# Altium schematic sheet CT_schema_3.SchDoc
size 321 x 189 mm
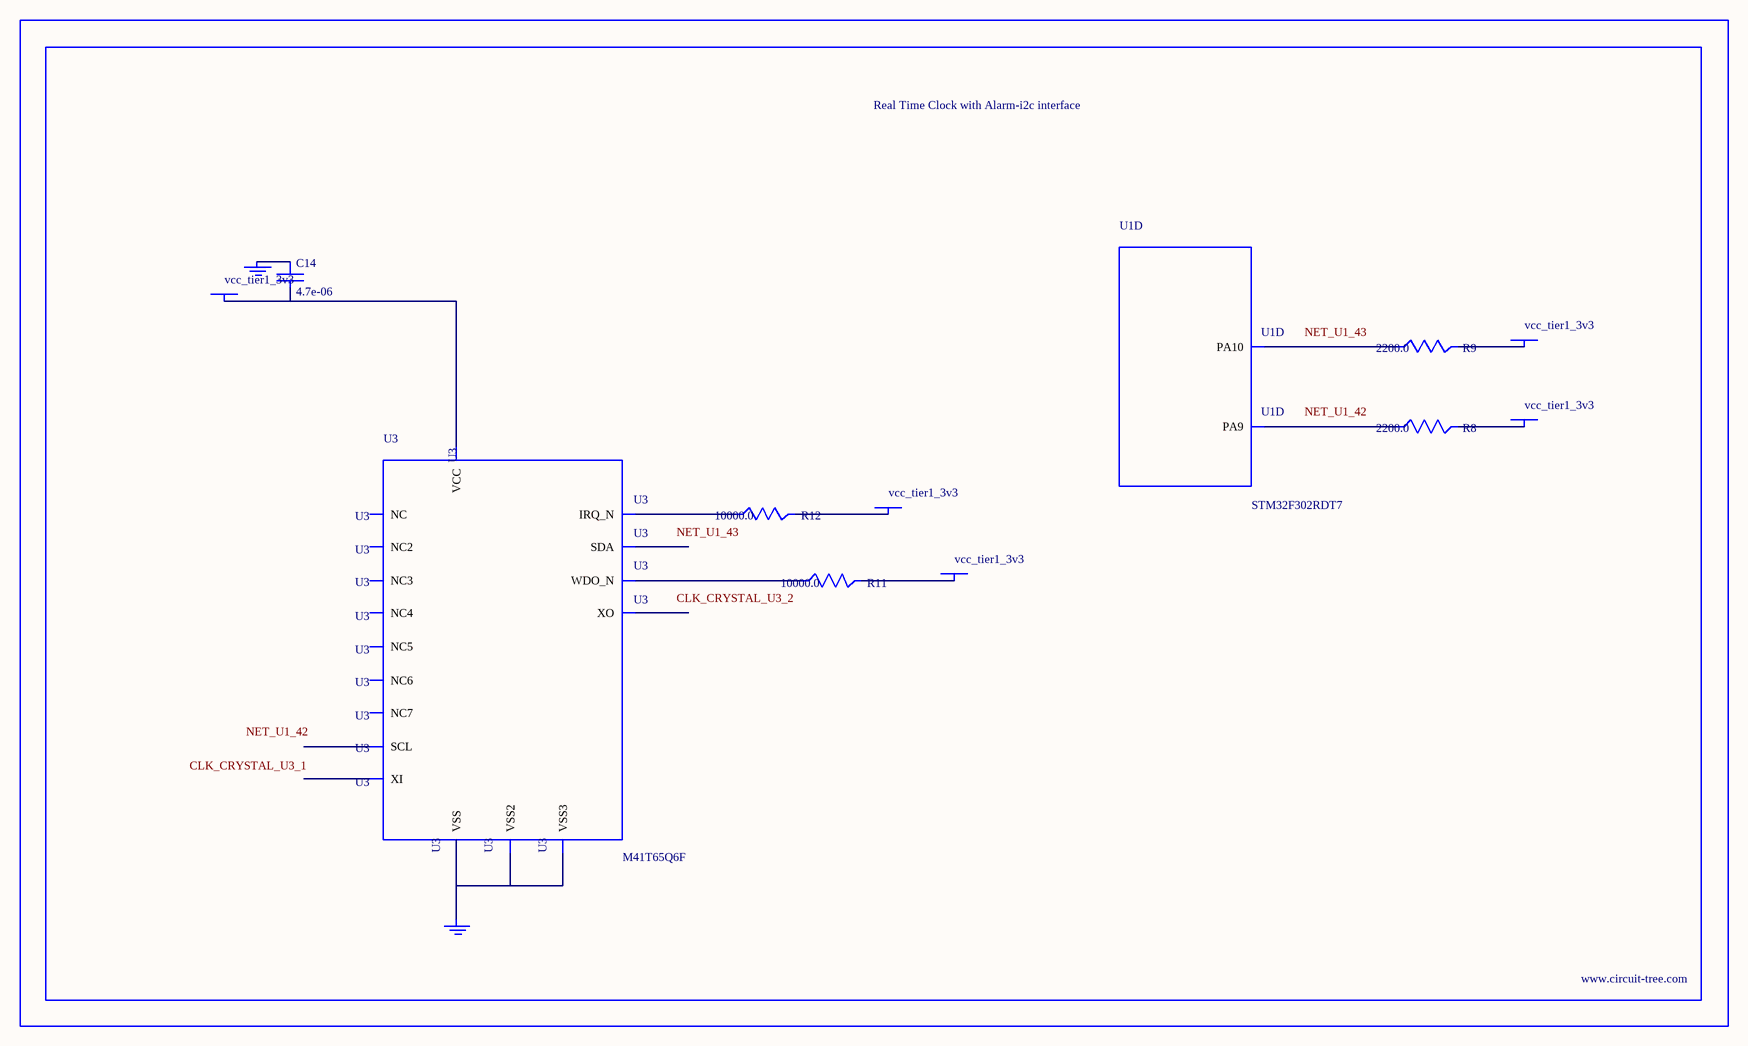
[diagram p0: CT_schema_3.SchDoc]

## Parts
BORDER2  (no value)
C14  4.7e-06  [C0805]
GND_INSTANCE_2_0  (no value)
GND_INSTANCE_2_1  (no value)
POWER_INSTANCE_2_0  vcc_tier1_3v3
POWER_INSTANCE_2_1  vcc_tier1_3v3
POWER_INSTANCE_2_2  vcc_tier1_3v3
POWER_INSTANCE_2_3  vcc_tier1_3v3
POWER_INSTANCE_2_4  vcc_tier1_3v3
R8  2200.0  [R0603]
R9  2200.0  [R0603]
R11  10000.0  [R0603]
R12  10000.0  [R0603]
U1  STM32F302RDT7  [LQFP64]  (part D of 7)
U3  M41T65Q6F  [M41T65_QFN-16]

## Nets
NetC14_1: C14.1 GND_INSTANCE_2_0.0(GND)
NetC14_2: C14.2 POWER_INSTANCE_2_2.0(PWR) U3.14(VCC)
NetGND_INSTANCE_2_1_0: GND_INSTANCE_2_1.0(GND) U3.3(VSS) U3.5(VSS2) U3.17(VSS3)
NetPOWER_INSTANCE_2_0_0: POWER_INSTANCE_2_0.0(PWR) R11.2
NetPOWER_INSTANCE_2_1_0: POWER_INSTANCE_2_1.0(PWR) R12.2
NetPOWER_INSTANCE_2_3_0: POWER_INSTANCE_2_3.0(PWR) R8.2
NetPOWER_INSTANCE_2_4_0: POWER_INSTANCE_2_4.0(PWR) R9.2
NetR8_1: R8.1 U1.42(PA9)
NetR9_1: R9.1 U1.43(PA10)
NetR11_1: R11.1 U3.4(WDO_N)
NetR12_1: R12.1 U3.11(IRQ_N)

Not connected (* = marked no-connect by the designer): U3 1(XI) 2(XO) 6(NC) 7(NC2) 8(NC3) 9(SDA) 10(SCL) 12(NC4) 13(NC5) 15(NC6) 16(NC7)

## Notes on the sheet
- Labels drawn without touching a wire or pin: CLK_CRYSTAL_U3_1, CLK_CRYSTAL_U3_2, NET_U1_42, NET_U1_43

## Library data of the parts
BORDER2 = BORDER_PAGE2
C14 = C0805C475K4RACTU
GND_INSTANCE_2_0 GND_INSTANCE_2_1 = GND
POWER_INSTANCE_2_0-POWER_INSTANCE_2_4 = PWR
R8 R9 = RC0603JR-072K2L
R11 R12 = RC0603JR-0710KL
